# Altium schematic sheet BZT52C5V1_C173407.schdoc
size 127 x 101 mm
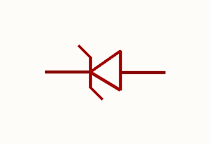
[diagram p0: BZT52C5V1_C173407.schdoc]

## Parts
D?  bzt52c5v1_c173407  [SOD-123_L2.7-W1.6-LS3.7-RD]  (value not drawn)

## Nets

Not connected (* = marked no-connect by the designer): D? 1(C) 2(A)

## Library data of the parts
D? = bzt52c5v1_c173407: 二极管配置:1个独立式;稳压值(标称值):5.1V;稳压值(范围):4.85V~5.36V;耗散功率(Pd):500mW;; Manufacturer: MDD(辰达半导体); AddInBom: yes; ModelId: ad7e39f9e5534b3c96ffdc5532ebb493; ModelName: SOD-123_L2.7-W1.6-H1.4-LS3.7; ModelTransform: 146.026,62.992,0,180,0,0,0.0005,0,0; Diode Configuration: 1个独立式; Zener Voltage(Nom): 5.1V; Reverse Leakage Current (Ir): 2uA; Pd - Power Dissipation: 500mW; Impedance(Zzt): 130Ω; Tolerance: ±5%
